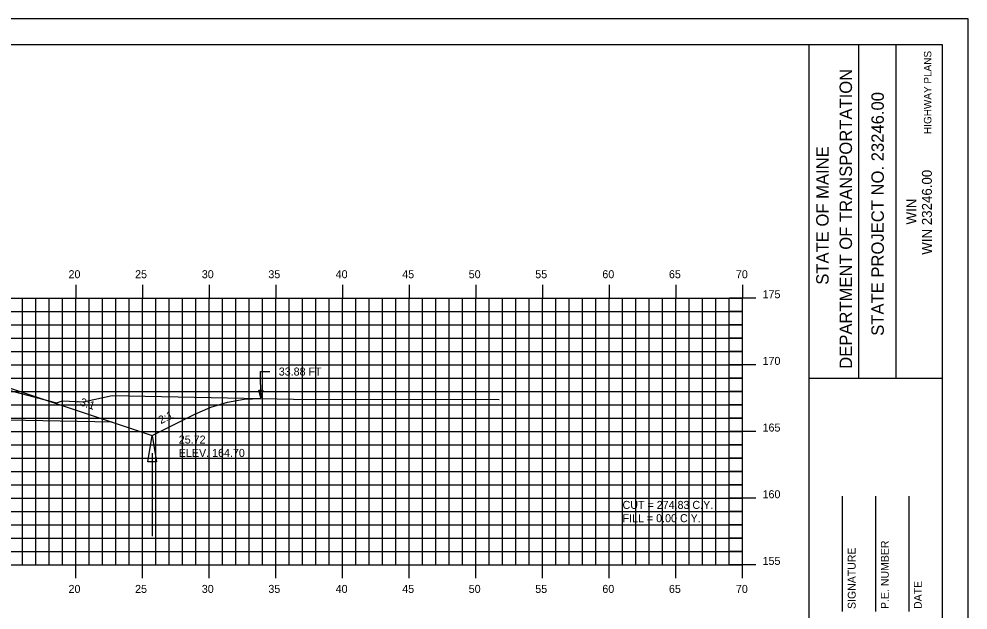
# Model space of a CAD drawing. Extents: x 1141868 to 1142038, y 608981 to 609091.
# Drawn here: x 1141966.5 to 1142037.7, y 609047 to 609091.3 of the extents above; entities that cross this region are included whole.
import ezdxf

# ---------------------------------------------------------------- set-up
doc = ezdxf.new("R2010")
doc.units = 0
for name, color, linetype in [('ANNOTATION', 7, 'Continuous'), ('BORDER', 7, 'Continuous'), ('D_Drainage_Ditch_Line', 7, 'Continuous'), ('D_Roadway_SlopeLines', 7, 'Continuous'), ('D_Roadway_SubGrade', 7, 'Continuous'), ('D_Text_Standard', 7, 'Continuous'), ('H_V ANNOTATION', 7, 'Continuous'), ('HIGHWAY_TITLE', 7, 'Continuous'), ('MAJOR', 7, 'Continuous'), ('MINOR', 7, 'Continuous'), ('PLOT BOUNDARY', 7, 'Continuous'), ('S_Roadway_Centerline', 7, 'Continuous')]:
    doc.layers.add(name, color=color, linetype=linetype)

msp = doc.modelspace()

# ---------------------------------------------------------------- linework, layer by layer
msp.add_lwpolyline([(1141915.849, 609063.427), (1141917.099, 609063.333), (1141918.349, 609063.087), (1141919.599, 609062.69), (1141920.849, 609062.141), (1141925.059, 609060.036), (1141928.059, 609061.036), (1141935.783, 609063.61), (1141935.784, 609063.61), (1141939.784, 609063.77), (1141950.784, 609063.99), (1141961.784, 609063.77), (1141965.784, 609063.61), (1141973.507, 609061.036), (1141976.507, 609060.036), (1141979.667, 609061.616), (1141980.917, 609062.159), (1141982.167, 609062.54), (1141983.417, 609062.758), (1141984.667, 609062.813)])
at = {"layer": 'BORDER'}
for p, q in [((1142025.784, 608984.335), (1142025.784, 609089.335)), ((1142029.513, 609064.332), (1142029.513, 609089.332)), ((1142032.308, 609064.332), (1142032.308, 609089.332)), ((1142025.785, 609064.329), (1142035.784, 609064.329)), ((1142028.284, 609046.838), (1142028.284, 609055.485)), ((1142030.784, 609046.838), (1142030.784, 609055.485)), ((1142033.284, 609046.838), (1142033.284, 609055.485))]:
    msp.add_line(p, q, dxfattribs=at)
msp.add_lwpolyline([(1141875.784, 608984.335), (1142035.784, 608984.335), (1142035.784, 609089.335), (1141875.784, 609089.335)], close=True, dxfattribs=at)
at = {"layer": 'D_Drainage_Ditch_Line'}
msp.add_line((1141976.507, 609058.724), (1141976.507, 609052.48), dxfattribs=at)
msp.add_lwpolyline([(1141976.835, 609058.067), (1141976.179, 609058.067), (1141976.507, 609060.036)], close=True, dxfattribs=at)
at = {"layer": 'D_Roadway_SlopeLines'}
for points in [[(1141976.507, 609060.036), (1141979.667, 609061.616), (1141980.917, 609062.159), (1141982.167, 609062.54), (1141983.417, 609062.758), (1141984.667, 609062.813)], [(1141973.507, 609061.036), (1141976.507, 609060.036)]]:
    msp.add_lwpolyline(points, dxfattribs=at)
at = {"layer": 'D_Roadway_SubGrade'}
msp.add_lwpolyline([(1141961.784, 609063.354), (1141961.784, 609063.52), (1141965.784, 609063.36), (1141965.784, 609063.61), (1141965.784, 609063.61), (1141973.507, 609061.036), (1141961.784, 609061.27)], close=True, dxfattribs=at)
at = {"layer": 'D_Text_Standard'}
msp.add_lwpolyline([(1141984.667, 609062.866), (1141984.644, 609064.836), (1141985.324, 609064.836)], dxfattribs=at)
msp.add_lwpolyline([(1141984.667, 609062.866), (1141984.515, 609063.446), (1141984.806, 609063.449)], close=True, dxfattribs=at)
at = {"layer": 'MAJOR'}
for p, q in [((1141970.784, 609071.337), (1141970.784, 609070.335)), ((1141975.784, 609071.337), (1141975.784, 609070.335)), ((1141980.784, 609071.337), (1141980.784, 609070.335)), ((1141985.784, 609071.337), (1141985.784, 609070.335)), ((1141990.784, 609071.337), (1141990.784, 609070.335)), ((1141995.784, 609071.337), (1141995.784, 609070.335)), ((1142000.784, 609071.337), (1142000.784, 609070.335)), ((1142005.784, 609071.337), (1142005.784, 609070.335)), ((1142010.784, 609071.337), (1142010.784, 609070.335)), ((1142015.784, 609071.337), (1142015.784, 609070.335)), ((1142020.784, 609071.337), (1142020.784, 609070.335)), ((1141880.784, 609070.335), (1142020.784, 609070.335)), ((1141880.784, 609070.335), (1142020.784, 609070.335)), ((1141970.784, 609050.335), (1141970.784, 609070.335)), ((1141975.784, 609050.335), (1141975.784, 609070.335)), ((1141980.784, 609050.335), (1141980.784, 609070.335)), ((1141985.784, 609050.335), (1141985.784, 609070.335)), ((1141990.784, 609050.335), (1141990.784, 609070.335)), ((1141995.784, 609050.335), (1141995.784, 609070.335)), ((1142000.784, 609050.335), (1142000.784, 609070.335)), ((1142005.784, 609050.335), (1142005.784, 609070.335)), ((1142010.784, 609050.335), (1142010.784, 609070.335)), ((1142015.784, 609050.335), (1142015.784, 609070.335)), ((1142021.786, 609070.335), (1142019.782, 609070.335)), ((1142020.784, 609050.335), (1142020.784, 609070.335)), ((1142020.784, 609050.335), (1142020.784, 609070.335)), ((1141880.784, 609065.335), (1142020.784, 609065.335)), ((1142021.786, 609065.335), (1142019.782, 609065.335)), ((1141880.784, 609060.335), (1142020.784, 609060.335)), ((1142021.786, 609060.335), (1142019.782, 609060.335)), ((1141880.784, 609055.335), (1142020.784, 609055.335)), ((1142021.786, 609055.335), (1142019.782, 609055.335)), ((1141880.784, 609050.335), (1142020.784, 609050.335)), ((1141880.784, 609050.335), (1142020.784, 609050.335)), ((1141970.784, 609049.333), (1141970.784, 609050.335)), ((1141975.784, 609049.333), (1141975.784, 609050.335)), ((1141980.784, 609049.333), (1141980.784, 609050.335)), ((1141985.784, 609049.333), (1141985.784, 609050.335)), ((1141990.784, 609049.333), (1141990.784, 609050.335)), ((1141995.784, 609049.333), (1141995.784, 609050.335)), ((1142000.784, 609049.333), (1142000.784, 609050.335)), ((1142005.784, 609049.333), (1142005.784, 609050.335)), ((1142010.784, 609049.333), (1142010.784, 609050.335)), ((1142015.784, 609049.333), (1142015.784, 609050.335)), ((1142021.786, 609050.335), (1142019.782, 609050.335)), ((1142020.784, 609049.333), (1142020.784, 609050.335))]:
    msp.add_line(p, q, dxfattribs=at)
at = {"layer": 'MINOR'}
for p, q in [((1141966.784, 609050.335), (1141966.784, 609070.335)), ((1141967.784, 609050.335), (1141967.784, 609070.335)), ((1141968.784, 609050.335), (1141968.784, 609070.335)), ((1141969.784, 609050.335), (1141969.784, 609070.335)), ((1141971.784, 609050.335), (1141971.784, 609070.335)), ((1141972.784, 609050.335), (1141972.784, 609070.335)), ((1141973.784, 609050.335), (1141973.784, 609070.335)), ((1141974.784, 609050.335), (1141974.784, 609070.335)), ((1141976.784, 609050.335), (1141976.784, 609070.335)), ((1141977.784, 609050.335), (1141977.784, 609070.335)), ((1141978.784, 609050.335), (1141978.784, 609070.335)), ((1141979.784, 609050.335), (1141979.784, 609070.335)), ((1141981.784, 609050.335), (1141981.784, 609070.335)), ((1141982.784, 609050.335), (1141982.784, 609070.335)), ((1141983.784, 609050.335), (1141983.784, 609070.335)), ((1141984.784, 609050.335), (1141984.784, 609070.335)), ((1141986.784, 609050.335), (1141986.784, 609070.335)), ((1141987.784, 609050.335), (1141987.784, 609070.335)), ((1141988.784, 609050.335), (1141988.784, 609070.335)), ((1141989.784, 609050.335), (1141989.784, 609070.335)), ((1141991.784, 609050.335), (1141991.784, 609070.335)), ((1141992.784, 609050.335), (1141992.784, 609070.335)), ((1141993.784, 609050.335), (1141993.784, 609070.335)), ((1141994.784, 609050.335), (1141994.784, 609070.335)), ((1141996.784, 609050.335), (1141996.784, 609070.335)), ((1141997.784, 609050.335), (1141997.784, 609070.335)), ((1141998.784, 609050.335), (1141998.784, 609070.335)), ((1141999.784, 609050.335), (1141999.784, 609070.335)), ((1142001.784, 609050.335), (1142001.784, 609070.335)), ((1142002.784, 609050.335), (1142002.784, 609070.335)), ((1142003.784, 609050.335), (1142003.784, 609070.335)), ((1142004.784, 609050.335), (1142004.784, 609070.335)), ((1142006.784, 609050.335), (1142006.784, 609070.335)), ((1142007.784, 609050.335), (1142007.784, 609070.335)), ((1142008.784, 609050.335), (1142008.784, 609070.335)), ((1142009.784, 609050.335), (1142009.784, 609070.335)), ((1142011.784, 609050.335), (1142011.784, 609070.335)), ((1142012.784, 609050.335), (1142012.784, 609070.335)), ((1142013.784, 609050.335), (1142013.784, 609070.335)), ((1142014.784, 609050.335), (1142014.784, 609070.335)), ((1142016.784, 609050.335), (1142016.784, 609070.335)), ((1142017.784, 609050.335), (1142017.784, 609070.335)), ((1142018.784, 609050.335), (1142018.784, 609070.335)), ((1142019.784, 609050.335), (1142019.784, 609070.335)), ((1141880.784, 609069.335), (1142020.784, 609069.335)), ((1142020.784, 609069.335), (1142019.782, 609069.335)), ((1141880.784, 609068.335), (1142020.784, 609068.335)), ((1142020.784, 609068.335), (1142019.782, 609068.335)), ((1141880.784, 609067.335), (1142020.784, 609067.335)), ((1142020.784, 609067.335), (1142019.782, 609067.335)), ((1141880.784, 609066.335), (1142020.784, 609066.335)), ((1142020.784, 609066.335), (1142019.782, 609066.335)), ((1141880.784, 609064.335), (1142020.784, 609064.335)), ((1142020.784, 609064.335), (1142019.782, 609064.335)), ((1141880.784, 609063.335), (1142020.784, 609063.335)), ((1142020.784, 609063.335), (1142019.782, 609063.335)), ((1141880.784, 609062.335), (1142020.784, 609062.335)), ((1142020.784, 609062.335), (1142019.782, 609062.335)), ((1141880.784, 609061.335), (1142020.784, 609061.335)), ((1142020.784, 609061.335), (1142019.782, 609061.335)), ((1141880.784, 609059.335), (1142020.784, 609059.335)), ((1142020.784, 609059.335), (1142019.782, 609059.335)), ((1141880.784, 609058.335), (1142020.784, 609058.335)), ((1142020.784, 609058.335), (1142019.782, 609058.335)), ((1141880.784, 609057.335), (1142020.784, 609057.335)), ((1142020.784, 609057.335), (1142019.782, 609057.335)), ((1141880.784, 609056.335), (1142020.784, 609056.335)), ((1142020.784, 609056.335), (1142019.782, 609056.335)), ((1141880.784, 609054.335), (1142020.784, 609054.335)), ((1142020.784, 609054.335), (1142019.782, 609054.335)), ((1141880.784, 609053.335), (1142020.784, 609053.335)), ((1142020.784, 609053.335), (1142019.782, 609053.335)), ((1141880.784, 609052.335), (1142020.784, 609052.335)), ((1142020.784, 609052.335), (1142019.782, 609052.335)), ((1141880.784, 609051.335), (1142020.784, 609051.335)), ((1142020.784, 609051.335), (1142019.782, 609051.335))]:
    msp.add_line(p, q, dxfattribs=at)
at = {"layer": 'PLOT BOUNDARY'}
msp.add_lwpolyline([(1141867.691, 608981.276), (1142037.691, 608981.276), (1142037.691, 609091.276), (1141867.691, 609091.276)], close=True, dxfattribs=at)
at = {"layer": 'S_Roadway_Centerline'}
msp.add_lwpolyline([(1141898.931, 609063.67), (1141920.641, 609063.358), (1141927.442, 609063.286), (1141928.262, 609063.104), (1141932.279, 609062.607), (1141933.177, 609062.83), (1141936.132, 609063.548), (1141937.343, 609063.608), (1141939.921, 609063.8), (1141947.871, 609063.896), (1141950.814, 609063.993), (1141959.278, 609063.846), (1141962.001, 609063.801), (1141964.008, 609063.742), (1141965.696, 609063.641), (1141965.824, 609063.405), (1141969.332, 609062.485), (1141969.794, 609062.639), (1141971.337, 609062.56), (1141973.519, 609063.048), (1141987.101, 609062.762), (1142002.535, 609062.728)], dxfattribs=at)

# ---------------------------------------------------------------- texts
at = {"layer": 'ANNOTATION'}
for s, rotation, p in [('-3:1', 341.56521, (1141970.795, 609062.394)), ('2:1', 26.56505, (1141977.16, 609060.88))]:
    msp.add_text(s, height=0.6, rotation=rotation, dxfattribs=at).set_placement(p)
at = {"layer": 'BORDER'}
for s, height, p in [('DEPARTMENT OF TRANSPORTATION', 0.93176, (1142028.991, 609065.041)), ('STATE PROJECT NO. 23246.00', 0.93176, (1142031.376, 609067.517)), ('STATE OF MAINE', 0.93176, (1142027.239, 609071.347)), ('WIN 23246.00', 0.74527, (1142034.98, 609073.596)), ('WIN', 0.7453, (1142033.821, 609075.865)), ('P.E. NUMBER', 0.59055, (1142031.745, 609047.03)), ('SIGNATURE', 0.5906, (1142029.264, 609047.03)), ('DATE', 0.5906, (1142034.225, 609047.03))]:
    msp.add_text(s, height=height, rotation=90, dxfattribs=at).set_placement(p)
at = {"layer": 'D_Text_Standard'}
for s, p in [('33.88 FT', (1141986.004, 609064.536)), ('25.72', (1141978.507, 609059.436)), ('ELEV. 164.70', (1141978.507, 609058.434)), ('CUT = 274.83 C.Y.', (1142011.784, 609054.535)), ('FILL = 0.00 C.Y.', (1142011.784, 609053.539))]:
    msp.add_text(s, height=0.6, dxfattribs=at).set_placement(p)
at = {"layer": 'H_V ANNOTATION'}
for s, p in [('20', (1141970.238, 609071.835)), ('25', (1141975.23, 609071.835)), ('30', (1141980.232, 609071.835)), ('35', (1141985.224, 609071.835)), ('40', (1141990.27, 609071.835)), ('45', (1141995.262, 609071.835)), ('50', (1142000.248, 609071.835)), ('55', (1142005.24, 609071.835)), ('60', (1142010.27, 609071.835)), ('65', (1142015.262, 609071.835)), ('70', (1142020.286, 609071.835)), ('175', (1142022.284, 609070.335)), ('170', (1142022.284, 609065.335)), ('165', (1142022.284, 609060.335)), ('160', (1142022.284, 609055.335)), ('155', (1142022.284, 609050.335)), ('20', (1141970.238, 609048.235)), ('25', (1141975.23, 609048.235)), ('30', (1141980.232, 609048.235)), ('35', (1141985.224, 609048.235)), ('40', (1141990.27, 609048.235)), ('45', (1141995.262, 609048.235)), ('50', (1142000.248, 609048.235)), ('55', (1142005.24, 609048.235)), ('60', (1142010.27, 609048.235)), ('65', (1142015.262, 609048.235)), ('70', (1142020.286, 609048.235))]:
    msp.add_text(s, height=0.6, dxfattribs=at).set_placement(p)
at = {"layer": 'HIGHWAY_TITLE'}
msp.add_text('HIGHWAY PLANS', height=0.55901, rotation=90, dxfattribs=at).set_placement((1142034.942, 609082.65))

doc.saveas('drawing.dxf')
